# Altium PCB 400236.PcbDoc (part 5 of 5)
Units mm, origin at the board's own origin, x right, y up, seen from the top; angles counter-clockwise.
Board outline 136.53 x 63.5 mm, 4 copper layers (Top Layer, Mid-Layer 1, Mid-Layer 2, Bottom Layer), stack 1.505 mm thick; 340 components, 230 nets, 1369 pads, 1292 vias.
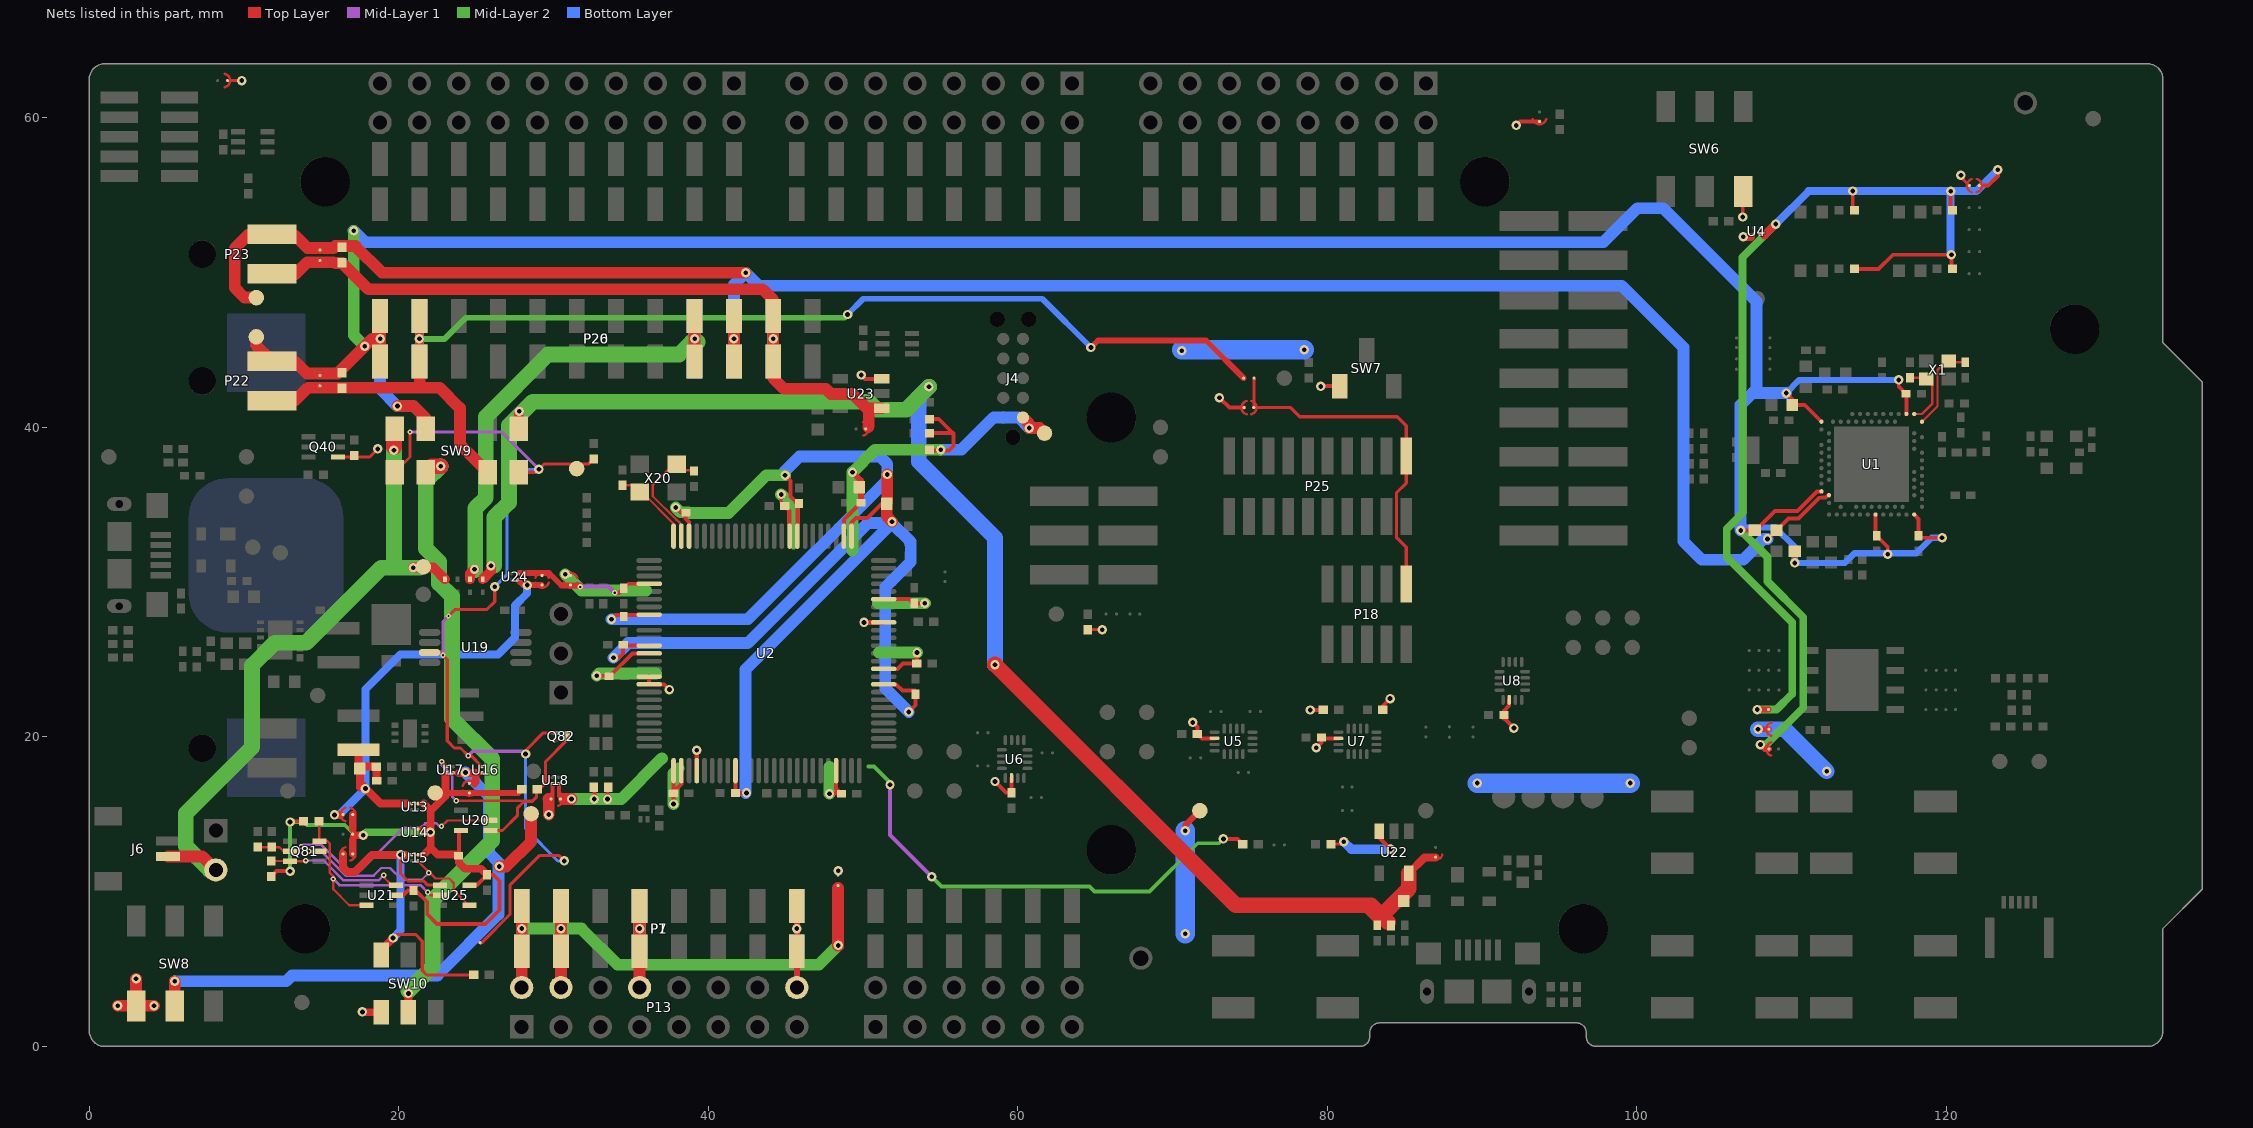
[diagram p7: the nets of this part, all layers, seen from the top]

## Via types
v1: diameter 0.61, hole 0.305, Top Layer to Bottom Layer, tented both sides, 1088 vias
v2: diameter 0.35, hole 0.15, Top Layer to Mid-Layer 1, tented both sides, 180 vias
v3: diameter 0.61, hole 0.305, Top Layer to Bottom Layer, 24 vias

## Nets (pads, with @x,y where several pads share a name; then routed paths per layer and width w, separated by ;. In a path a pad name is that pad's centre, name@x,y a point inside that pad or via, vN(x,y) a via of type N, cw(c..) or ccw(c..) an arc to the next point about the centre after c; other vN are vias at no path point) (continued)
VBUS_NRF': C68.2 C91.2 D81.2 FB60.2 SB80.2 SW9.8 U22.5 | length 100
  Top Layer w0.508: U22.5@85.253,11.198 86.272,12.217 SB80.2@86.995,12.217
  Top Layer w0.635: D81.2@25.425,30.186 25.959,30.719 v1(25.959,31.064) ; SW9.8@27.749,39.906 27.749,41.008 v1(27.788,41.046)
  Top Layer w1.016: v1(58.522,24.673) 74.076,9.119 82.634,9.119 ; 83.497,8.44 85.253,10.196 U22.5@85.253,11.198 ; 83.666,8.271 83.315,8.621 83.223,8.529 82.634,9.119 ; FB60.2@83.91,8.026 82.818,9.119 82.634,9.119
  Mid-Layer 2 w1.016: v1@26.162,31.064 26.162,34.188 27.127,35.154 27.127,40.132 28.651,41.656 50.368,41.656 50.876,41.148 52.781,41.148 v1(54.254,42.621)
  Bottom Layer w1.016: v1(54.254,42.621) 53.594,41.961 53.594,37.795 58.522,32.868 v1(58.522,24.673)
VCORE: C24.2 C26.2 C32.1 C33.2 C35.2 C39.2 C40.2 U2.9 U2.34 U2.52 U2.59 U2.73 U2.83 U2.87 | length 120.1
  Top Layer w0.254: v1(33.747,27.598) 34.038,27.889 U2.83@36.168,27.889 ; v1(33.874,25.121) 34.232,25.121 34.501,25.389 C24.2@34.501,25.959 ; C24.2@34.67,25.9 U2.87@36.179,25.9 ; v1(37.897,34.823) 38.227,34.493 C32.1@38.531,34.493 ; C32.1@38.555,34.493 C32.1@38.531,34.493 ; U2.73@38.754,32.975 38.754,33.89 38.531,34.113 C32.1@38.531,34.493 ; C33.2@41.75,16.383 v1(42.469,16.383) ; C33.2@41.754,16.4 U2.9@41.754,17.825 ; v1(44.958,36.906) 45.314,36.551 45.314,35.525 45.466,35.373 C35.2@45.808,35.031 ; U2.59@45.754,32.975 45.754,34.977 C35.2@45.808,35.031 ; C35.2@45.862,35.085 C35.2@45.808,35.031 ; U2.52@49.254,32.975 49.254,33.861 49.531,34.138 50.292,34.138 51.232,35.077 C39.2@51.522,35.077 ; U2.34@51.329,23.4 52.13,23.4 52.543,22.987 C40.2@53.338,22.987 ; v1(52.949,21.615) 53.381,22.047 C40.2@53.381,22.766 ; C40.2@53.363,22.827 C40.2@53.363,22.987
  Top Layer w0.762: v1(51.562,36.957) 51.562,35.117 C39.2@51.522,35.077 51.522,34.254 v1(51.867,33.909)
  Mid-Layer 2 w0.762: v1(37.897,34.823) 38.202,34.519 38.718,34.519 38.769,34.468 41.3,34.468 43.739,36.906 v1(44.958,36.906)
  Bottom Layer w0.762: v1(33.747,27.598) 42.558,27.598 51.562,36.601 v1(51.562,36.957) 51.562,37.643 51.079,38.125 45.898,38.125 44.958,37.186 v1(44.958,36.906) ; v1(33.874,25.121) 34.813,26.06 42.535,26.06 50.292,33.817 v1@51.867,33.817 ; v1@42.416,16.383 42.408,16.391 42.408,24.359 v1@51.867,33.817 ; v1(52.949,21.615) 51.425,23.139 51.425,29.671 53.076,31.322 53.076,32.608 v1@51.867,33.817
VDBG: P18.1 P25.1 SB59.1 SB60.1 | length 23
  Top Layer w0.203: SB60.1@75.268,43.18 75.268,41.607 75.268,41.3 SB59.1@75.242,41.275 75.417,41.275 77.622,41.275 78.207,40.691 84.506,40.691 85.09,40.107 P25.1@85.09,38.145 85.09,36.398 84.455,35.763 84.455,32.893 85.09,32.258 P18.1@85.09,29.89
VDD: C42.2 C45.2 C48.2 C50.2 Q40.4 R41.1 R52.1 R53.1 R54.2 R68.2 SB9.1 SB17.1 SB31.1 SB37.2 SB38.2 SB47.1 SB59.2 SW6.6 SW7.3 SW8.3 SW10.6 TP37.1 U4.A2 U5.14 U6.14 U7.14 U8.14 U18.A2 U22.3 U23.3 | length 69.9
  Top Layer w0.2: SB47.1@8.923,62.408 v1(9.855,62.408) ; Q40.4@16.063,38.085 18.121,38.085 v1(18.644,38.608) ; R68.2@64.516,26.932 v1(65.448,26.932) ; R54.2@80.231,13.081 80.899,13.081 v1(81.051,13.233) ; v1(120.929,56.286) 120.929,56.179 SB9.1@121.489,55.619
  Top Layer w0.254: 29.941,15.992 U18.A2@29.941,16.95 ; v1(49.886,43.383) 50.129,43.139 U23.3@51.21,43.139 ; v1(58.522,17.12) 59.241,16.4 C45.2@59.588,16.4 59.592,16.404 U6.14@59.592,17.342 ; v1(71.306,20.938) 71.306,20.922 71.595,20.633 C42.2@71.595,20.193 71.88,19.907 U5.14@72.707,19.907 ; v1(73.025,41.91) 73.66,41.275 74.443,41.275 SB59.2@74.618,41.275 ; v1@78.892,21.717 78.918,21.742 R53.1@79.739,21.742 ; v1(79.273,19.304) 79.621,19.652 C48.2@79.621,19.964 79.675,19.91 U7.14@80.715,19.91 ; v1(79.578,42.647) 79.597,42.665 SW7.3@80.8,42.665 ; U22.3@83.353,13.898 83.353,13.472 v1(84.074,12.751) ; R52.1@83.583,21.742 83.583,22.014 v1(84.049,22.479) v1@84.074,22.504 ; C50.2@91.389,21.192 91.508,21.311 C50.2@91.407,21.412 ; U8.14@91.748,22.397 91.737,22.386 91.737,22.021 91.407,21.69 C50.2@91.407,21.412 ; v1(92.05,20.574) 91.411,21.213 91.407,21.217 C50.2@91.407,21.412 ; v1(92.202,59.512) 92.448,59.759 SB31.1@93.701,59.759 ; v1(106.832,53.594) 106.832,54.948 SW6.6@106.869,54.984 ; 107.292,52.225 U4.A2@107.537,52.47
  Top Layer w0.381: v1(70.815,13.945) 70.815,14.3 TP37.1@71.755,15.24 ; v1(107.823,20.498) 108.352,20.498 SB17.1@108.527,20.498
  Top Layer w0.508: v1(17.653,2.235) 17.674,2.214 SW10.6@18.875,2.214 ; v1@106.858,52.299 107.366,52.299
  Top Layer w0.762: v1(1.848,2.628) v1(4.185,2.628) ; SW8.3@3.027,2.559 v1(3.027,4.369) ; 29.679,15.992 29.693,15.979 v1(29.693,14.986)
  Bottom Layer w0.61: v1(81.051,13.233) 81.534,12.751 v1(84.074,12.751)
  Bottom Layer w1.016: v1(107.823,20.498) 109.55,20.498 v1(112.268,17.78)
  Bottom Layer w1.27: v1@70.587,45.009 v1(78.511,45.009) ; v1(70.815,7.29) v1(70.815,13.945) ; v1(89.687,17.018) v1(99.568,17.018)
  other v1: 48.387,11.354 78.892,21.742 70.587,44.958 106.858,52.324
VDD_HV: C19.1 P20.10 P23.1 P26.10 R91.2 SB41.1 TP25.1 U1.Y2 | length 134.4
  Top Layer w0.25: v1@108.562,32.708 108.562,32.891 C19.1@109.014,33.342 109.783,34.112 110.447,34.112 111.793,35.458 111.989,35.458 112.179,35.459 112.337,35.617 U1.Y2@112.414,35.617
  Top Layer w0.762: TP25.1@10.795,48.387 10.033,48.387 9.398,49.022 9.398,51.562 10.306,52.47 P23.1@11.811,52.47 ; P23.1@11.811,52.4 13.284,52.4 14.089,51.595 15.781,51.595 15.9,51.714 17.196,51.714 18.923,49.987 v1(42.418,49.987) ; P20.10@41.656,44.255 v1(41.656,45.72) P20.10@41.656,47.185
  Bottom Layer w0.762: P26.10@41.656,44.255 v1(41.656,45.72) P26.10@41.656,47.185 41.656,49.225 v1(42.418,49.987) 43.256,49.149 99.023,49.149 102.997,45.175 102.997,32.639 104.188,31.448 106.863,31.448 108.206,32.791 v1(108.433,32.791)
VDD_HV': P20.11 P23.2 P26.11 R91.1 SB41.2 SB81.1 U23.1 | length 50.7
  Top Layer w0.762: P23.2@11.811,49.86 13.284,49.86 14.089,50.665 15.781,50.665 ; 15.91,50.613 16.349,50.613 18.042,48.92 43.51,48.92 44.196,48.235 P20.11@44.196,47.185 v1(44.196,45.72) P20.11@44.196,44.255 44.196,43.18 44.882,42.494 47.585,42.494 47.915,42.164 49.301,42.164 50.226,41.239 ; 50.333,40.016 50.368,40.051 50.368,41.097 50.226,41.239 ; U23.1@51.21,41.239 50.226,41.239
  Bottom Layer w0.762: P26.11@44.196,44.255 v1(44.196,45.72) P26.11@44.196,47.185
VDD_NRF: C6.1 C7.1 C8.1 C12.1 C14.1 L4.1 P20.1 P22.1 P26.1 R90.2 SB18.1 SB40.1 SW9.6 TP24.1 U1.A22 U1.AD14 U1.AD23 U1.B1 U1.W1 | length 200.6
  Top Layer w0.25: v1(106.714,33.342) C6.1@107.613,33.342 107.664,33.342 108.916,34.595 110.371,34.595 111.641,35.865 U1.W1@111.914,35.865 ; v1(109.639,42.217) 110.039,41.817 C14.1@110.039,41.444 110.837,41.444 U1.B1@111.914,40.367 ; v1@110.189,31.117 L4.1@110.189,31.992 ; C7.1@115.414,32.992 U1.AD14@115.414,34.367 ; C7.1@115.49,32.992 116.205,32.277 v1@116.205,32.004 ; v1(116.915,43.067) 116.915,42.641 C12.1@117.389,42.167 117.414,42.142 U1.A22@117.414,40.867 ; U1.AD23@117.914,34.367 118.189,34.092 C8.1@118.189,32.992 118.313,32.868 v1(119.71,32.868)
  Top Layer w0.381: v1(107.975,19.507) 108.255,19.228 108.352,19.228 SB18.1@108.527,19.228
  Top Layer w0.762: TP24.1@10.795,45.847 10.795,45.286 P22.1@11.811,44.27 13.284,44.27 14.064,43.49 16.058,43.49 v1(17.805,45.237) 18.288,45.72 v1(18.796,45.72) ; P20.1@18.796,44.255 v1(18.796,45.72) ; P20.1@18.796,47.185 v1(18.796,45.72) ; v1(19.914,41.377) 20.955,41.377 21.749,40.583 SW9.6@21.749,39.906
  Mid-Layer 2 w0.508: v1(106.714,33.342) 108.433,31.623 108.433,30.048 110.744,27.737 110.744,21.895 108.356,19.507 v1(107.975,19.507)
  Mid-Layer 2 w0.762: v1@17.094,52.685 17.094,45.949 v1(17.805,45.237)
  Bottom Layer w0.4: v1(106.714,33.342) 106.894,33.522 108.946,33.522 110.189,32.28 v1@110.189,31.318 ; v1(109.639,42.217) 110.489,43.067 v1@116.839,43.067 ; v1(110.189,31.244) 113.427,31.244 114.054,31.871 118.054,31.871 119.05,32.868 v1(119.71,32.868)
  Bottom Layer w0.762: v1(17.084,52.71) 17.838,51.956 97.828,51.956 100.025,54.153 101.702,54.153 107.729,48.126 107.729,42.493 ; P26.1@18.796,47.185 v1(18.796,45.72) P26.1@18.796,44.255 18.796,42.494 v1(19.914,41.377) ; v1(106.714,33.342) 106.692,33.364 106.692,41.456 107.729,42.493 ; v1(109.639,42.217) 107.729,42.217 107.729,42.493
  other v1: 116.205,31.801
VDD_NRF': P20.2 P22.2 P26.2 R90.1 SB40.2 SB60.2 SW9.3 | length 82.3
  Top Layer w0.381: v1(64.719,45.161) 65.176,45.618 72.154,45.618 SB60.2@74.592,43.18
  Top Layer w0.508: P20.2@21.336,44.255 v1(21.336,45.72) P20.2@21.336,47.185
  Top Layer w0.762: P22.2@11.811,41.73 13.284,41.73 14.115,42.561 21.361,42.561 ; P20.2@21.336,44.255 21.361,44.23 21.361,42.561 ; SW9.3@25.749,37.106 23.952,38.903 23.952,41.25 22.641,42.561 21.361,42.561
  Mid-Layer 2 w0.381: v1(21.336,45.72) 22.963,45.72 24.325,47.081 48.783,47.081 v1(48.997,47.295)
  Bottom Layer w0.381: v1(48.997,47.295) 50.013,48.311 61.57,48.311 v1(64.719,45.161)
  Bottom Layer w0.508: P26.2@21.336,44.255 v1(21.336,45.72) P26.2@21.336,47.185
VDD_NRF_SENSE: Q82.1 R88.1 SB58.1 SW9.1 SW9.4 TP33.1 U16.B2 U19.3 | length 67.2
  Top Layer w0.203: SW9.1@19.749,37.106 20.726,38.084 v2(20.726,39.7) ; U19.3@21.993,25.456 22.677,25.456 v2(22.86,25.273) 23.129,25.004 23.129,19.747 23.591,19.284 23.987,19.284 v2(24.486,18.786) 24.673,18.786 U16.B2@25.378,18.082 ; v2(23.216,27.813) 23.647,28.245 25.705,28.245 26.2,28.74 v1(26.2,29.705) ; SB58.1@25.255,6.706 25.356,6.706 27.178,8.528 27.178,10.408 29.117,12.347 30.325,12.347 v1(30.683,11.989) ; SW9.4@27.749,37.106 28.877,37.106 v1(29.058,37.287) 29.413,37.643 32.275,37.643 R88.1@32.588,37.956 ; v1(28.194,18.898) 28.194,19.126 29.333,20.266 Q82.1@30.155,20.266
  Mid-Layer 1 w0.203: v2(20.726,39.7) 26.645,39.7 v1(29.058,37.287) ; v2(22.86,25.273) 22.86,27.457 v2(23.216,27.813) ; v2(24.486,18.786) 24.775,19.075 28.016,19.075 v1(28.194,18.898)
  Bottom Layer w0.203: v1(26.2,29.705) 27,30.505 27,36.297 27.991,37.287 v1(29.058,37.287) ; v1(28.194,18.898) 28.194,14.078 30.283,11.989 v1(30.683,11.989)
VDD_PER: R47.2 R48.2 R50.2 R51.2 SB9.2 SB16.1 U4.A1 | length 71
  Top Layer w0.25: U4.A1@107.95,52.476 108.235,52.476
  Top Layer w0.254: R50.2@113.94,50.353 R50.2@114.059,50.234 115.614,50.234 116.535,51.156 v1(120.316,51.156) 120.316,50.302 R51.2@120.384,50.234 ; 113.94,54.443 v1(113.94,55.271) 113.94,54.163 R47.2@114.059,54.044 ; v1(120.265,55.264) 120.265,54.163 R48.2@120.384,54.044 ; SB9.2@122.114,55.619 122.289,55.619 122.684,55.619 123.317,56.252 v1(123.317,56.642)
  Top Layer w0.381: v1(107.772,21.768) SB16.1@108.501,21.768
  Top Layer w0.508: 108.229,52.4 v1(108.966,53.137)
  Mid-Layer 2 w0.508: v1(107.772,21.768) 109.017,21.768 110.033,22.784 110.033,27.395 105.804,31.623 105.804,33.44 106.819,34.455 106.819,50.99 v1(108.966,53.137)
  Bottom Layer w0.508: v1(108.966,53.137) 111.093,55.264 v1(120.265,55.264) ; v1@120.265,51.156 v1(120.265,55.264) ; v1(123.317,56.642) 121.939,55.264 v1(120.265,55.264)
VDD_SAM: C25.2 C31.2 C34.2 C36.2 C37.2 C38.2 C41.2 C43.2 J4.1 R20.2 R21.2 R49.2 R64.2 R65.2 R66.2 SB37.1 SB49.1 TP35.1 U2.1 U2.2 U2.4 U2.22 U2.36 U2.42 U2.45 U2.53 U2.60 U2.88 U2.91 U2.92 U18.A1 | length 117.8
  Top Layer w0.152: U2.88@36.179,25.4 U2.88@36.347,25.4
  Top Layer w0.203: v1(44.704,35.67) 44.704,35.161 C34.2@44.94,34.925
  Top Layer w0.254: 30.347,16.196 30.347,16.407 U18.A1@30.347,16.958 ; v1@32.636,16.002 R20.2@32.636,16.747 ; v1(32.791,23.952) 33.645,23.952 35.093,25.4 U2.88@36.179,25.4 ; v1(33.486,15.985) R21.2@33.486,16.747 ; U2.91@36.179,23.9 U2.92@36.179,23.4 37.151,23.4 v1(37.489,23.062) ; U2.1@37.754,17.825 37.754,16.358 37.756,16.356 v1(37.756,15.666) ; C31.2@37.76,16.459 38.254,16.954 U2.2@38.254,17.825 ; C34.2@44.94,34.925 45.254,34.611 U2.60@45.254,32.975 ; v1(47.828,16.332) C36.2@48.598,16.332 48.254,16.676 U2.22@48.254,17.825 ; U2.53@48.754,32.975 48.754,34.032 49.017,34.295 49.763,35.041 C37.2@49.763,35.128 ; U2.36@51.329,24.4 52.228,24.4 52.568,24.74 C41.2@53.465,24.74 53.482,24.757 v1(53.482,25.451) ; U2.42@51.329,27.4 U2.42@51.348,27.381 ; U2.45@51.329,28.9 52.98,28.9 C43.2@53.17,28.71 ; C43.2@53.305,28.634 v1(53.99,28.634) ; R64.2@54.293,38.557 R64.2@54.297,38.557 54.297,38.506 55.55,38.506 55.829,38.786 55.829,39.599 55.804,39.624 ; R65.2@54.293,39.624 R65.2@54.297,39.624 55.804,39.624 ; R66.2@54.297,40.538 54.889,40.538 55.804,39.624 ; v1(73.279,13.411) 74.201,13.411 R49.2@74.532,13.081
  Top Layer w0.305: U2.4@39.254,17.825 v1(39.254,19.146) ; v1(50.059,27.4) U2.42@51.329,27.4
  Top Layer w0.381: v1(49.317,37.109) 49.868,36.559 C37.2@49.868,35.128
  Top Layer w0.762: 30.678,15.992 v1(31.16,15.992) ; J4.1@60.325,40.64 60.731,40.234 v1(60.731,39.954) 61.417,39.954 TP35.1@61.747,39.624
  Mid-Layer 1 w0.254: v1(51.74,16.916) 51.74,13.665 v1(54.432,10.973)
  Mid-Layer 2 w0.254: 50.343,18.085 50.698,18.085 51.74,17.043 v1(51.74,16.916) ; v1(54.432,10.973) 55.07,10.335 64.625,10.335 64.94,10.02 68.513,10.02 71.622,13.129 72.997,13.129 v1(73.279,13.411)
  Mid-Layer 2 w0.762: v1(30.759,30.505) 31.801,29.464 35.992,29.464 ; v1@31.16,15.985 v1(33.486,15.985) 34.377,15.985 37.004,18.612 ; v1(32.791,23.952) 32.937,24.098 36.623,24.098 ; v1(37.756,15.666) 37.756,17.639 38.075,17.958 ; v1(44.704,35.67) 45.513,34.861 45.513,32.48 ; v1(47.828,16.332) 47.828,18.053 ; 49.317,32.045 v1(49.317,37.109) 50.765,38.557 v1(55.008,38.557) ; 50.948,28.634 v1(53.99,28.634) ; 51.024,25.451 v1(53.482,25.451)
  Bottom Layer w0.762: v1(55.008,38.557) 56.354,38.557 58.437,40.64 60.046,40.64 v1(60.731,39.954)
  other v1: 32.636,15.985
VDD_UTMI: C28.2 SB48.1 SB49.2 U2.79 U24.A1 | length 9.2
  Top Layer w0.254: v2@31.681,29.787 v2@31.775,29.693 ; v2(33.95,29.312) 34.237,29.312 C28.2@34.534,29.608 ; C28.2@34.542,29.616 34.826,29.9 U2.79@36.179,29.9
  Top Layer w0.381: 27.788,30.596 29.704,30.596 30.513,29.787 30.757,29.787 31.422,29.787 v2@31.681,29.787
  Mid-Layer 1 w0.254: v2@31.725,29.718 33.543,29.718 v2(33.95,29.312)
  other v2: 31.725,29.693
VEXT: R92.1 SB36.2 SW10.3 U15.A1 U25.1 | length 24.1
  Top Layer w0.203: SW10.3@18.875,5.914 SW10.3@18.875,6.251 ; 19.84,7.241 21.08,7.241 21.514,6.807 21.514,4.928 21.819,4.623 R92.1@24.849,4.623 ; v1(20.117,12.382) 20.117,11.176 20.599,10.693 21.615,10.693 21.88,10.429 U25.1@22.672,10.429
  Top Layer w0.245: 20.498,12.392 U15.A1@20.831,12.392
  Top Layer w0.508: SB36.2@16.393,12.446 16.393,12.183 16.403,12.173 16.403,12.159 ; 16.403,12.159 16.403,11.563 16.688,11.278 17.17,11.278 18.275,12.382 v1(20.117,12.382) 20.488,12.382 ; SW10.3@18.875,6.251 v1(19.634,7.01)
  Bottom Layer w0.508: v1(19.634,7.01) 20.117,7.493 v1(20.117,12.382)
VEXT_EN: Q81.5 U15.B2 U25.4 | length 14.5
  Top Layer w0.152: v2(14.199,12.624) Q81.5@14.869,12.624 ; U15.B2@21.231,11.992 22.367,10.856 23.256,10.856 23.546,10.566 23.546,10.104 U25.4@24.521,9.129
  Mid-Layer 1 w0.152: v2(14.199,12.624) 14.979,12.624 16.564,11.039 18.379,11.039 18.87,11.529 19.433,11.529 20.193,10.77 21.488,10.77 v2(21.946,11.227)
VEXT_EN_INV: Q81.3 R89.2 U21.6 | length 9.1
  Top Layer w0.152: R89.2@11.76,11.981 12.962,11.981 Q81.3@12.969,11.974 13.955,11.974 v2(13.995,12.014) ; v2(19.025,11.074) 19.025,10.937 19.533,10.429 U21.6@19.822,10.429
  Mid-Layer 1 w0.152: v2(13.995,12.014) 15.157,12.014 16.437,10.734 18.684,10.734 v2(19.025,11.074)
VIN: P1.8 P7.8 P13.16 | length 8.2
  Top Layer w0.381: P13.16@45.72,3.81 P1.8@45.72,6.155 v1(45.72,7.62) P1.8@45.72,9.085
  Bottom Layer w0.381: P7.8@45.72,6.155 v1(45.72,7.62) P7.8@45.72,9.085
VIN3-5V: D83.2 P20.9 P26.9 | length 32.5
  Top Layer w0.635: D83.2@24.613,30.186 24.613,30.556 v1(24.892,30.836)
  Top Layer w0.762: P20.9@39.116,44.255 v1(39.116,45.72) P20.9@39.116,47.185
  Mid-Layer 2 w1.016: v1@24.943,30.785 24.943,34.773 25.629,35.458 25.629,40.691 29.642,44.704 38.1,44.704 38.913,45.517 v1@39.319,45.517
  Bottom Layer w0.762: P26.9@39.116,44.255 v1(39.116,45.72) P26.9@39.116,47.185
VIO: P1.1 P1.2 P1.4 P7.1 P7.2 P7.4 P13.2 P13.4 P13.8 SB38.1 | length 54.1
  Top Layer w0.381: v1(35.56,7.62) P1.4@35.56,9.085
  Top Layer w0.762: P13.2@27.94,3.81 P1.1@27.94,6.155 P1.1@27.94,9.085 ; P13.4@30.48,3.81 v1(30.48,7.62) P1.2@30.48,9.085 ; P13.8@35.56,3.81 P1.4@35.56,9.085 ; v1(48.387,6.528) 48.387,10.236
  Mid-Layer 2 w0.762: v1(27.94,7.62) v1(30.48,7.62) 31.801,7.62 34.138,5.283 35.535,5.283 ; v1(35.56,7.62) 35.56,5.309 35.535,5.283 ; v1(48.387,6.528) 47.142,5.283 35.535,5.283
  Bottom Layer w0.762: P7.1@27.94,6.155 P7.1@27.94,9.085 ; P7.2@30.48,6.155 P7.2@30.48,9.085 ; P7.4@35.56,6.155 P7.4@35.56,9.085
VLI-ION: D82.2 J6.2 P27.2 SW9.5 TP31.1 | length 44.1
  Top Layer w0.635: v1(20.93,30.937) 22.235,30.937 D82.2@22.987,30.186
  Top Layer w0.762: J6.2@5.105,12.276 7.307,12.276 P27.2@8.179,11.405
  Top Layer w1.016: v1@19.685,38.735 19.685,39.842 SW9.5@19.749,39.906
  Mid-Layer 2 w1.016: P27.2@8.179,11.405 7.772,11.405 6.236,12.941 6.236,15.05 10.516,19.329 10.516,24.613 11.989,26.086 14.021,26.086 18.872,30.937 19.685,30.937 ; v1(19.685,38.532) 19.685,30.937 ; 21.336,30.937 v1(20.93,30.937) 19.685,30.937
VREG: C87.2 C88.2 L81.2 R82.2 SB34.2 SB48.2 U13.A1 U24.A2 | length 34.2
  Top Layer w0.245: 20.498,15.694 U13.A1@20.831,15.694
  Top Layer w0.381: 27.788,30.062 27.774,30.062 28.024,29.812 v1(28.296,29.812) 28.908,29.812 SB48.2@29.235,29.812
  Top Layer w0.508: v1(15.85,14.961) 16.228,14.961 16.23,14.959 ; L81.2@17.399,19.093 17.399,18.049 C88.2@17.49,17.958 ; 17.49,16.739 C88.2@17.49,17.958 ; 17.49,17.018 v1(17.845,16.662) 18.814,15.694 20.498,15.694 ; C87.2@18.575,17.17 18.55,17.196 R82.2@18.55,18.085 17.617,18.085 C88.2@17.49,17.958
  Bottom Layer w0.508: v1(15.85,14.961) 16.144,14.961 v1(17.845,16.662) 17.845,23.078 20.091,25.324 26.406,25.324 27.508,26.426 27.508,28.499 28.296,29.286 v1(28.296,29.812)
VREG_EN: Q81.2 R83.2 R85.1 U20.2 | length 17.5
  Top Layer w0.152: R85.1@10.893,12.886 10.893,12.87 12.294,12.87 12.541,12.624 Q81.2@12.969,12.624 13.411,12.624 v2(13.691,12.903) ; v2(22.758,14.224) 23.139,14.605 U20.2@25.918,14.605
  Mid-Layer 1 w0.152: v2(13.691,12.903) 13.812,13.025 15.008,13.025 16.69,11.343 17.504,11.343 20.283,14.122 21.412,14.122 21.717,14.427 22.428,14.427 22.631,14.224 v2(22.758,14.224)
VREG_EN_INV: Q81.6 R86.2 U21.3 U25.2 | length 15
  Top Layer w0.152: R86.2@14.851,14.554 14.851,13.292 15.359,13.292 15.548,13.103 15.548,11.205 15.773,10.98 v2(15.773,10.82) 15.773,10.16 16.804,9.129 U21.3@17.922,9.129 ; v2(21.869,9.957) 22.047,9.779 U25.2@22.672,9.779
  Mid-Layer 1 w0.152: v2(15.773,10.82) 16.165,10.429 21.397,10.429 v2(21.869,9.957)
VSENSE_SW_OUT: SB39.1 SW8.2 TP30.1 U16.A2 U17.A1 | length 41.3
  Top Layer w0.25: U17.A1@23.517,17.682 23.876,17.682 ; 24.971,17.682 U16.A2@25.378,17.682
  Top Layer w0.508: 23.876,17.682 24.971,17.682 24.971,17.08 24.892,17
  Top Layer w0.762: SW8.2@5.528,2.609 v1(5.528,4.216) ; v1(26.492,11.633) 26.949,11.633 28.55,13.233 TP30.1@28.55,14.859
  Bottom Layer w0.762: v1(5.528,4.216) 12.727,4.216 13.106,4.596 22.503,4.596 26.441,8.534 26.441,11.909 25.829,12.521 25.829,16.182 v1(24.308,17.704)
VSRC_NRF: SW9.2 SW10.5 | length 40.6
  Top Layer w0.508: SW10.5@20.625,2.214 v1(20.625,3.429)
  Top Layer w1.016: SW9.2@21.749,37.106 22.133,37.49 v1(22.708,37.49)
  Mid-Layer 2 w1.016: v1@20.625,3.607 22.174,5.156 22.174,9.449 26.035,13.31 26.035,18.593 23.444,21.184 23.444,29.083 22.606,29.921 22.606,31.32 21.749,32.177 21.749,36.532 v1(22.708,37.49)
VSUPPLY: C89.2 C90.2 C93.2 R86.1 R87.1 R89.1 SB34.1 SB35.1 SB36.1 SB39.2 TP29.1 U13.A2 U14.A2 U15.A2 U17.A2 U20.5 U21.5 U25.5 | length 49.4
  Top Layer w0.245: U15.A2@21.231,12.392 21.615,12.392 ; U14.A2@21.231,14.043 21.615,14.043 ; U13.A2@21.231,15.694 21.641,15.694
  Top Layer w0.254: R89.1@11.76,10.981 12.108,11.328 v1(12.979,11.328) ; v1(12.979,14.503) 13.03,14.554 R86.1@13.851,14.554 ; U21.5@19.822,9.779 20.295,9.779 20.591,10.076 C89.2@20.955,10.076 21.09,10.076 21.842,9.324 21.842,8.562 22.481,7.922 25.601,7.922 26.497,8.819 26.497,10.688 26.111,11.074 25.722,11.074 C90.2@25.705,11.092 25.042,10.429 U25.5@24.521,10.429 ; C93.2@23.884,12.395 23.884,13.821 U20.5@24.018,13.955
  Top Layer w0.381: 23.012,16.386 23.012,16.391 23.937,16.391 23.942,16.386 24.201,16.386 24.922,16.386 27.722,16.386 R87.1@27.948,16.612
  Top Layer w0.457: SB36.1@17.028,12.446 17.028,13.365 ; 17.028,14.067 SB34.1@17.028,14.986
  Top Layer w0.508: SB35.1@17.091,13.65 v1(17.704,13.65) ; 21.615,12.392 22.07,12.846 ; 21.615,14.043 22.067,14.043 v1@22.07,14.046 ; 21.641,15.694 21.641,15.666 22.07,15.237 ; 23.012,16.386 23.012,16.18 22.07,15.237 ; 23.012,16.391 23.012,17.501 ; C90.2@25.705,11.092 25.316,11.481 24.282,11.481 23.884,11.879 23.884,12.395 22.521,12.395 22.07,12.846 ; 22.07,12.846 v1@22.07,14.046 ; v1@22.07,14.046 22.07,15.237
  Mid-Layer 2 w0.254: v1(12.979,11.328) v1(12.979,14.503) 13.868,14.503 14.072,14.3 16.51,14.3 17.16,13.65 v1(17.704,13.65)
  Mid-Layer 2 w0.508: v1(17.704,13.65) 17.897,13.843 v1(22.047,13.843)
VSUPPLY_EN: Q82.3 R87.2 U17.B2 U20.1 | length 16.8
  Top Layer w0.152: v2(22.784,18.415) U17.B2@23.117,18.082 ; v2(23.724,15.875) 27.983,15.875 28.059,15.799
  Top Layer w0.203: U20.1@25.918,13.955 26.706,13.955 27.661,14.91 27.661,15.4 28.059,15.799 28.11,15.85 28.626,15.85 28.905,16.129 28.905,16.62 29.066,16.62 29.489,17.043 29.489,18.415 30.855,19.781 Q82.3@30.855,20.041
  Mid-Layer 1 w0.152: v2(22.784,18.415) 22.784,18.161 23.444,17.501 23.444,16.154 v2(23.724,15.875)
XC1: C1.1 U1.B24 X1.1 | length 5.8
  Top Layer w0.152: U1.B24@118.414,40.367 119.414,41.367 119.414,43.717 119.909,44.213 C1.1@121.203,44.213
XC2: C2.1 U1.A23 X1.3 | length 4.3
  Top Layer w0.152: C2.1@117.647,43.213 118.625,43.213 X1.3@118.7,43.138 119.089,42.749 119.089,41.538 118.418,40.867 U1.A23@117.914,40.867
XIN: C29.1 U2.75 X20.3 | length 5.1
  Top Layer w0.152: C29.1@34.458,36.254 35.162,36.254 X20.3@35.575,35.841 ; X20.3@35.575,35.838 35.694,35.838 37.754,33.778 U2.75@37.754,32.975
XOUT: C30.1 U2.74 X20.1 | length 7.5
  Top Layer w0.152: U2.74@38.254,32.975 38.254,33.729 38.1,33.884 37.955,34.029 37.934,34.029 36.414,35.549 36.414,36.287 37.746,37.619 X20.1@37.963,37.619 38.354,37.228 C30.1@39.081,37.228
pads on no net: Bat1.0 Fid1.0 Fid2.0 J2.4 J2.6@1.944,28.45 J2.6@1.944,35.05 J3.4 J3.6@86.429,3.557 J3.6@93.029,3.557 J4.0 J4.7 J4.9 J5.0 J5.1 J5.3 J5.5 J6.0 P18.7 P18.8 P19.7 P19.8 P21.0 P22.0 P23.0 P25.7 P25.8 P25.11 P25.13 SW8.1 U2.6 U2.8 U2.10 U2.11 U2.13 U2.15 U2.16 U2.19 U2.25 U2.26 U2.28 U2.29 U2.30 U2.31 U2.32 U2.33 U2.37 U2.44 U2.48 U2.49 U2.50 U2.58 U2.64 U2.69 U2.86 U2.93 U2.94 U2.95 U2.96 U2.99 U2.100 U5.1 U5.5 U5.9 U5.13 U6.1 U6.5 U6.9 U6.13 U7.7 U7.11 U8.11 U8.12 U8.13 U12.5 U22.4 U23.4
copper on no net: | length 3.6
  Bottom Layer w0.254: 38.252,53.76 38.252,57.379

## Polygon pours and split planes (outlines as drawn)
VDD on Mid-Layer 2 "Mid_Layer_2-VDD" (solid, remove dead copper, pour order 10): -3.81,-3.81 -3.81,68.58 138.43,68.58 138.43,-3.81
VDD_SAM on Mid-Layer 2 "Mid_Layer_2-VDD_SAM" (solid, pour order 8): 35.837,33.12 35.837,17.379 51.555,17.379 51.555,33.12
GND on Bottom Layer "Bottom_Layer-GND" (solid, remove dead copper, pour order 6): -3.81,-3.81 -3.81,68.58 138.43,68.58 138.43,-3.81
GND on Mid-Layer 1 "Mid_Layer_1-GND" (solid, remove dead copper, pour order 7): -3.81,-3.81 -3.81,68.58 138.43,68.58 138.43,-3.81
GND on Top Layer "Top_Layer-GND" (solid, remove dead copper, pour order 12): -3.81,-3.81 -3.81,68.58 138.43,68.58 138.43,-3.81

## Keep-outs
Top Layer:
  lines w0.152: 16.336,8.023 ccw(c13.97,7.62) 16.339,8.006 ; 68.406,13.103 ccw(c66.04,12.7) 68.409,13.086 ; 90.89,53.591 cw(c90.17,55.88) 91.893,54.209
Mid-Layer 1:
  circle w0.152: c66.04,12.7 r2.4
  circle w0.152: c90.17,55.88 r2.4
  circle w0.152: c13.97,7.62 r2.4
Mid-Layer 2:
  circle w0.152: c90.17,55.88 r2.4
  circle w0.152: c13.97,7.62 r2.4
  lines w0.152: 65.381,10.392 cw(c66.04,12.7) 66.72,10.398
Bottom Layer:
  circle w0.152: c66.04,12.7 r2.4
  circle w0.152: c90.17,55.88 r2.4
  circle w0.152: c13.97,7.62 r2.4
Keep-Out Layer:
  circle w0.152: c128.27,46.355 r2.4
  circle w0.152: c15.24,55.88 r2.4
  circle w0.152: c66.04,40.64 r2.4
  circle w0.152: c96.52,7.62 r2.4
  circle w0.1: c13.967,0 r0.3
  circle w0.1: c15.067,0 r0.3
  circle w0.1: c16.167,0 r0.3
  circle w0.1: c123.987,0 r0.3
  circle w0.1: c122.887,0 r0.3
  circle w0.1: c121.787,0 r0.3
  circle w0.1: c136.526,42.025 r0.3
  circle w0.1: c136.526,40.926 r0.3
  circle w0.1: c136.526,39.826 r0.3
  circle w0.1: c121.787,63.5 r0.3
  circle w0.1: c122.887,63.5 r0.3
  circle w0.1: c123.987,63.5 r0.3
  circle w0.1: c13.967,63.5 r0.3
  circle w0.1: c15.067,63.5 r0.3
  circle w0.1: c16.167,63.5 r0.3
  circle w0.1: c0,48.692 r0.3
  circle w0.1: c0,49.792 r0.3
  circle w0.1: c0,50.891 r0.3
  circle w0.1: c0,17.705 r0.3
  circle w0.1: c0,18.804 r0.3
  circle w0.1: c0,19.904 r0.3
  lines w0.254: 0,1.016 ccw(c1.016,1.016) 1.016,0 82.099,0 ccw(c82.099,0.635) 82.734,0.635 82.734,0.889 cw(c83.369,0.889) 83.369,1.524 96.09,1.524 cw(c96.09,0.889) 96.725,0.889 96.725,0.635 ccw(c97.36,0.635) 97.36,0 132.969,0 ccw(c132.969,1.016) 133.985,1.016 133.985,7.62 136.525,10.16 136.525,42.926 133.985,45.466 133.985,62.484 ccw(c132.969,62.484) 132.969,63.5 1.016,63.5 ccw(c1.016,62.484) 0,62.484 0,1.016

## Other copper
Top Layer:
  rectangle net ANT: 134.92,20.343 136.19,21.105
  rectangle net GND: 8.484,25.527 12.167,26.594
  rectangle net GND: 11.557,24.308 13.132,28.397
  pour cut-out: 24.34,36.179 34.579,36.18 cw(c34.58,33.644) 36.375,35.436 38.509,33.302 cw(c36.718,31.508) 39.253,31.506 39.253,31.237 cw(c37.043,31.237) 37.043,29.027 34.834,29.027 cw(c34.833,30.64) 33.693,29.5 31.579,31.613 ccw(c30.81,30.846) 30.808,31.933 24.328,31.933 cw(c135.433,33.762)
  pour cut-out: 13.807,35.551 cw(c15.316,34.043) 15.316,36.176 25.908,36.176 25.908,31.939 16.574,31.92 ccw(c16.747,30.866) 15.922,31.544 14.783,30.405 13.807,30.405
  pour cut-out: 9.86,34.155 11.774,34.155 11.938,34.155 11.938,30.013 11.169,30.013 cw(c11.169,30.94) 10.513,30.284 ccw(c10.035,29.809) 10.034,30.482 5.422,30.482 5.422,34.158 7.355,34.158 7.411,34.148 7.465,34.13 7.51,34.104 7.553,34.069 7.584,34.023 7.602,33.98 7.607,33.934 7.607,32.685 9.354,32.685 9.354,33.65 cw(c9.86,33.65)
  pour cut-out: 11.677,34.155 12.282,34.155 ccw(c12.282,34.476) 12.509,34.249 13.819,35.56 14.795,35.56 14.795,30.414 cw(c13.804,31.435) 13.782,30.013 11.677,30.013
  pour cut-out: 90.658,5.004 90.658,7.315 96.62,7.315 96.62,5.004
  pour cut-out: 91.161,32.131 91.161,33.401 89.891,33.401 89.891,32.131
  pour cut-out: 107.164,32.217 107.164,33.617 110.834,33.617 110.834,32.217
  pour cut-out: 110.664,31.367 110.664,32.867 113.164,32.867 113.164,31.367
  pour cut-out: 115.414,36.867 115.414,38.367 117.914,38.367 117.914,36.867
  pour cut-out: 117.737,33.63 116.676,34.691 118.444,36.458 119.505,35.398
  pour cut-out: 60.528,30.937 68.073,30.937 68.071,32.715 60.528,32.715
  pour cut-out: 129.92,-1.27 136.786,-1.27 136.748,45.415 129.925,45.415
  pour cut-out: -0.229,28.204 2.824,28.204 2.818,35.281 -0.228,35.281
  pour cut-out: 28.981,25.603 28.981,26.873 27.711,26.873 27.711,25.603
  pour cut-out: 118.567,26.975 117.297,26.975 117.297,25.705 118.567,25.705
  pour cut-out: 11.252,51.765 9.982,51.765 9.982,50.495 11.252,50.495
  pour cut-out: 86.385,35.687 85.115,35.687 85.115,34.417 86.385,34.417
  pour cut-out: 60.757,53.086 48.387,53.086 48.387,51.816 60.757,51.816
  pour cut-out: 107.163,43.256 107.163,44.526 105.054,44.526 105.054,43.256
  pour cut-out: 22.149,1.168 22.149,2.438 20.879,2.438 20.879,1.168
  pour cut-out: 20.447,5.715 20.447,6.985 19.177,6.985 19.177,5.715
  pour cut-out: 20.218,1.143 20.218,3.264 18.948,3.264 18.948,1.143
  pour cut-out: 11.252,43.635 9.982,43.635 9.982,42.365 11.252,42.365
  pour cut-out: 118.496,37.293 121.239,37.293 121.239,39.142 120.439,39.142 120.439,40.188 118.496,40.188
Mid-Layer 1:
  pour cut-out: 110.28,18.44 107.467,18.44 107.467,25.333 110.28,25.333
  pour cut-out: 28.315,29.007 28.315,31.318 32.137,31.318 32.137,29.007
  pour cut-out: 92.078,58.763 92.078,61.074 95.377,61.074 95.377,58.763
  pour cut-out: 48.603,38.976 48.603,41.288 50.978,41.288 50.978,38.976
  pour cut-out: 85.782,11.379 85.782,13.691 88.157,13.691 88.157,11.379
  pour cut-out: 110.28,27.254 110.28,21.336 106.28,21.336 106.28,27.254
  pour cut-out: 129.92,-1.27 136.786,-1.27 136.748,45.415 129.925,45.415
  pour cut-out: 121.71,25.984 121.71,20.066 117.71,20.066 117.71,25.984
  pour cut-out: 104.44,46.723 110.357,46.723 110.357,42.723 104.44,42.723
  pour cut-out: 15.45,11.278 15.45,16.104 17.824,16.104 17.824,11.278
  pour cut-out: 23.4,15.494 23.4,17.805 25.774,17.805 25.774,15.494
  pour cut-out: 75.724,11.938 75.724,14.249 78.098,14.249 78.098,11.938
  pour cut-out: 56.725,19.202 56.725,21.514 59.099,21.514 59.099,19.202
  pour cut-out: 56.598,17.094 56.598,19.406 58.972,19.406 58.972,17.094
  pour cut-out: 60.618,17.843 60.618,20.155 62.992,20.155 62.992,17.843
  pour cut-out: 59.969,14.973 59.969,17.285 62.344,17.285 62.344,14.973
  pour cut-out: 64.878,26.695 64.878,29.007 68.656,29.007 68.656,26.695
  pour cut-out: 120.612,48.831 120.612,57.137 122.987,57.137 122.987,48.831
  pour cut-out: 7.449,61.138 7.449,63.449 9.823,63.449 9.823,61.138
  pour cut-out: 70.263,17.45 70.263,19.761 72.637,19.761 72.637,17.45
  pour cut-out: 71.438,20.587 71.438,22.898 73.812,22.898 73.812,20.587
  pour cut-out: 74.175,20.512 74.175,22.823 76.549,22.823 76.549,20.512
  pour cut-out: 73.369,16.612 73.369,18.923 75.744,18.923 75.744,16.612
  pour cut-out: 28.448,14.884 28.448,17.196 31.747,17.196 31.747,14.884
  pour cut-out: 54.212,29.184 54.212,31.495 56.586,31.495 56.586,29.184
  pour cut-out: 80.042,13.995 80.042,18.161 82.416,18.161 82.416,13.995
  pour cut-out: 84.979,19.177 84.979,21.488 90.941,21.488 90.941,19.177
  pour cut-out: 13.678,49.898 13.678,52.21 16.053,52.21 16.053,49.898
  pour cut-out: 13.704,41.87 13.704,44.181 16.078,44.181 16.078,41.87
  pour cut-out: 47.232,9.614 47.232,11.925 49.606,11.925 49.606,9.614
  pour cut-out: 23.654,5.486 23.654,7.798 26.028,7.798 26.028,5.486
  pour cut-out: 73.641,41.986 73.641,44.298 76.016,44.298 76.016,41.986
  pour cut-out: 73.667,40.03 73.667,42.342 76.041,42.342 76.041,40.03
  pour cut-out: 131.445,36.392 119.918,36.392 119.918,40.392 131.445,40.392
Mid-Layer 2:
  pour cut-out: 129.92,-1.27 136.786,-1.27 136.748,45.415 129.925,45.415
  pour cut-out: 131.445,36.392 119.918,36.392 119.918,40.392 131.445,40.392
Bottom Layer:
  pour cut-out: 129.92,-1.27 136.786,-1.27 136.748,45.415 129.925,45.415
  pour cut-out: 35.56,27.407 34.29,27.407 34.29,26.137 35.56,26.137

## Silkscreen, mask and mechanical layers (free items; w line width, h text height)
Top Overlay:
  drawing of 82 lines, arcs and shapes, not listed
  text "nRF ONLY" at 97.765,62.052 h1.78
  text "DEFAULT" at 104.877,62.052 h1.78
  text "GND" at 91.389,61.709 h1.78
  text "GND" at 11.125,61.62 h1.78
  text ".PCBNumber" at 116.028,61.468 h2.03
  text ".PCBRevision" at 116.093,60.165 h1.52
  text "GND" at 123.698,58.42 h1.78
  text "LED1" at 109.622,54.654 h2.03
  text "LED2" at 115.82,54.654 h2.03
  text "Debug out" at 0.406,54.127 h2.03
  text "P0.11" at 87.757,52.781 h1.78
  text "P0.12" at 99.568,52.781 h1.78
  text "LED3" at 109.495,50.869 h2.03
  text "LED4" at 115.845,50.869 h2.03
  text "VDD_HV" at 1.016,50.775 h1.4
  text "P0.13" at 87.757,50.241 h1.78
  text "P0.14" at 99.568,50.241 h1.78
  text "P0.27" at 19.304,49.886 h1.78 r90
  text "P0.26" at 21.844,49.886 h1.78 r90
  text "P0.02" at 24.384,49.886 h1.78 r90
  text "GND" at 26.924,49.886 h1.78 r90
  text "P1.15" at 29.464,49.886 h1.78 r90
  text "P1.14" at 32.004,49.886 h1.78 r90
  text "P1.13" at 34.544,49.886 h1.78 r90
  text "P1.12" at 37.084,49.886 h1.78 r90
  text "P1.11" at 39.624,49.886 h1.78 r90
  text "P1.10" at 42.164,49.886 h1.78 r90
  text "P1.08" at 46.228,49.886 h1.78 r90
  text "P1.07" at 48.768,49.886 h1.78 r90
  text "P1.06" at 51.308,49.886 h1.78 r90
  text "P1.05" at 53.848,49.886 h1.78 r90
  text "P1.04" at 56.388,49.886 h1.78 r90
  text "P1.03" at 58.928,49.886 h1.78 r90
  text "P1.02" at 61.468,49.886 h1.78 r90
  text "P0.10" at 69.088,49.886 h1.78 r90
  text "P0.09" at 71.628,49.886 h1.78 r90
  text "P0.08" at 74.168,49.886 h1.78 r90
  text "P0.07" at 76.708,49.886 h1.78 r90
  text "P0.06" at 79.248,49.886 h1.78 r90
  text "P0.05" at 81.788,49.886 h1.78 r90
  text "P0.01" at 84.328,49.886 h1.78 r90
  text "P0.00" at 86.868,49.886 h1.78 r90
  text "P0.15" at 87.757,47.701 h1.78
  text "P0.16" at 99.568,47.701 h1.78
  text "nRF current" at 0.965,47.193 h2.03
  text "measurement" at 0.483,45.898 h2.03
  text "Alt." at 79.756,45.339 h1.78
  text "Def." at 83.439,45.339 h1.78
  text "P0.17" at 87.757,45.161 h1.78
  text "P0.18" at 99.568,45.161 h1.78
  text "GPIO" at 102.997,44.958 h1.52
  text "XTAL" at 102.997,43.688 h1.52
  text "P0.19" at 87.757,42.621 h1.78
  text "P0.20" at 99.568,42.621 h1.78
  text "VDD" at 1.016,42.57 h1.4
  text "VTG" at 24.308,41.056 h1.4 r90
  text "VDD / nRF" at 19.761,40.98 h1.4 r90
  text "VDD / nRF'" at 22.301,40.98 h1.4 r90
  text "(ARDUINO D0) P1.01" at 64.059,40.777 h1.78 r90
  text "SWD / IO" at 27.508,40.752 h1.4 r90
  text "SWD / CLK" at 30.048,40.752 h1.4 r90
  text "SWO" at 31.928,40.74 h1.4 r90
  text "TRACE" at 80.391,40.513 h1.78
  text "P0.21" at 87.757,40.081 h1.78
  text "P0.22" at 99.568,40.081 h1.78
  text "VIN / 3-5V" at 40.081,39.993 h1.4 r90
  text "RESET" at 34.519,39.811 h1.4 r90
  text "VDD / nRF_HV" at 42.621,39.028 h1.4 r90
  text "VDD / nRF_HV'" at 45.161,39.028 h1.4 r90
  text "GND / DETECT" at 37.617,38.963 h1.4 r90
  text "P0.23" at 87.757,37.541 h1.78
  text "P0.24" at 99.568,37.541 h1.78
  text "P1.14" at 57.767,35.082 h1.52
  text "5V" at 69.248,35.031 h1.52
  text "P0.25" at 87.757,35.001 h1.78
  text "P1.00" at 99.568,35.001 h1.78
  text "Li-Po   VDD   USB" at 18.313,34.95 h1.78
  text "nRF power source" at 17.424,33.299 h2.03
  text "P1.13" at 69.248,32.567 h1.52
  text "P1.15" at 57.717,32.542 h1.52
  text "P1.09" at 87.757,32.461 h1.78
  text "GND" at 99.568,32.461 h1.78
  text "DETECT" at 69.16,30.074 h1.52
  text "RESET" at 56.955,30.002 h1.52
  text "Debug in" at 79.477,23.12 h2.03
  text "External supply" at 0.279,22.454 h2.03
  text "SB20-22" at 106.934,22.225 h1.52 r90
  text "SB10-12" at 110.465,22.225 h1.52 r90
  text "SB13-15" at 118.364,21.463 h1.52 r90
  text "SB23-25" at 121.92,21.463 h1.52 r90
  text "-" at 13.741,19.939 h1.52
  text "+" at 13.741,17.399 h1.52
  text "Button 1" at 102.594,17.19 h2.29
  text "Button 2" at 112.641,17.19 h2.29
  text "Li-po" at 3.251,15.088 h2.03
  text "-" at 5.715,13.513 h1.02
  text "+" at 5.715,10.973 h1.02
  text "N.C." at 46.253,10.465 h1.78 r90
  text "VDD" at 28.365,10.462 h1.78 r90
  text "VDD" at 30.905,10.462 h1.78 r90
  text "RESET" at 33.445,10.462 h1.78 r90
  text "VDD" at 35.985,10.462 h1.78 r90
  text "5V" at 38.525,10.462 h1.78 r90
  text "GND" at 41.065,10.462 h1.78 r90
  text "GND" at 43.605,10.462 h1.78 r90
  text "P0.03 (A0)" at 51.225,10.462 h1.78 r90
  text "P0.04" at 53.765,10.462 h1.78 r90
  text "P0.28" at 56.305,10.462 h1.78 r90
  text "P0.29" at 58.845,10.462 h1.78 r90
  text "P0.30" at 61.385,10.462 h1.78 r90
  text "P0.31" at 63.925,10.462 h1.78 r90
  text "NFC" at 123.123,9.926 h2.29
  text "Button 4" at 112.691,8.011 h2.29
  text "Button 3" at 102.518,8 h2.29
  text "IF BOOT/RESET" at 71.907,7.785 h2.03
  text "nRF USB" at 86.298,7.131 h2.29
  text "VEXT   nRF" at 16.662,6.909 h2.03
  text "GND" at 69.393,5.156 h1.78
  text "Power" at 11.506,3.2 h2.03 r90
  text "nRF52840-DK" at 132.283,0.914 h2.54 r90
  text "GND" at 68.402,0.761 h1.78
  text "ON" at 2.911,0.229 h1.78
  text "OFF" at 5.655,0.229 h1.78
  text "OFF" at 18.009,0.203 h1.78
  text "ON" at 21.438,0.203 h1.78
Bottom Overlay:
  drawing of 1284 lines, arcs and shapes, not listed
  text "J-Link" at 117.897,62.424 h1.45 r90
  text "www.segger.com" at 119.047,62.343 h1.68 r90
  text "Pb" at 6.415,60.623 h3.05 r90
  text "TM" at 117.475,58.954 h0.94 r90
  text "S" at 116.037,58.741 h1.35 r90
  text "E" at 116.037,57.851 h1.35 r90
  text "Technology" at 117.897,57.672 h1.45 r90
  text "G" at 116.037,57.067 h1.35 r90
  text "G" at 116.037,56.077 h1.35 r90
  text "E" at 116.037,55.053 h1.35 r90
  text "R" at 116.037,54.217 h1.35 r90
  text "P0.27" at 19.303,53.111 h1.65 r90
  text "P0.26" at 21.843,53.111 h1.65 r90
  text "P0.02" at 24.383,53.111 h1.65 r90
  text "GND" at 26.924,53.111 h1.65 r90
  text "P1.15" at 29.463,53.111 h1.65 r90
  text "P1.14" at 32.003,53.111 h1.65 r90
  text "P1.13" at 34.543,53.111 h1.65 r90
  text "P1.12" at 37.083,53.111 h1.65 r90
  text "P1.11" at 39.623,53.111 h1.65 r90
  text "P1.10" at 42.163,53.111 h1.65 r90
  text "P1.08" at 46.227,53.111 h1.65 r90
  text "P1.07 (D6)" at 48.768,53.111 h1.65 r90
  text "P1.06 (D5)" at 51.308,53.111 h1.65 r90
  text "P1.05 (D4)" at 53.848,53.111 h1.65 r90
  text "P1.04 (D3)" at 56.388,53.111 h1.65 r90
  text "P1.03 (D2)" at 58.928,53.111 h1.65 r90
  text "P1.02 (D1)" at 61.468,53.111 h1.65 r90
  text "P1.01 (ARDUINO D0)" at 64.008,53.111 h1.65 r90
  text "P0.10" at 69.088,53.111 h1.78 r90
  text "P0.09" at 71.628,53.111 h1.78 r90
  text "P0.08" at 74.168,53.111 h1.78 r90
  text "P0.07" at 76.708,53.111 h1.78 r90
  text "P0.06" at 79.248,53.111 h1.78 r90
  text "P0.05" at 81.788,53.111 h1.78 r90
  text "P0.01" at 84.328,53.111 h1.78 r90
  text "P0.00" at 86.843,53.111 h1.78 r90
  text "(SCL)" at 20.421,52.07 h1.65 r90
  text "(SDA)" at 22.961,52.07 h1.65 r90
  text "(AREF)" at 25.501,52.07 h1.65 r90
  text "(D13)" at 30.581,52.07 h1.65 r90
  text "(D12)" at 33.121,52.07 h1.65 r90
  text "(D11)" at 35.661,52.07 h1.65 r90
  text "(D10)" at 38.201,52.07 h1.65 r90
  text "(D9)" at 40.741,52.07 h1.65 r90
  text "(D8)" at 43.281,52.07 h1.65 r90
  text "(D7)" at 47.345,52.07 h1.65 r90
  text "GPIO" at 76.911,48.701 h1.99 r90
  text "P0.00" at 80.747,48.641 h1.91 r90
  text "P0.01" at 86.131,48.641 h1.91 r90
  text "P0.11" at 90.17,48.641 h1.91 r90
  text "P0.12" at 92.862,48.641 h1.91 r90
  text "P0.24" at 95.555,48.641 h1.91 r90
  text "P0.25" at 98.247,48.641 h1.91 r90
  text "P0.13" at 100.94,48.641 h1.91 r90
  text "P0.14" at 103.632,48.641 h1.91 r90
  text "P0.15" at 106.324,48.641 h1.91 r90
  text "P0.16" at 109.017,48.641 h1.91 r90
  text "P0.17" at 111.709,48.641 h1.91 r90
  text "P0.19" at 114.402,48.641 h1.91 r90
  text "P0.20" at 117.094,48.641 h1.91 r90
  text "P0.21" at 119.786,48.641 h1.91 r90
  text "P0.22" at 122.479,48.641 h1.91 r90
  text "P0.23" at 125.171,48.641 h1.91 r90
  text "Function" at 76.911,43.231 h1.99 r90
  text "Button 4" at 98.247,42.965 h1.91 r90
  text "Button 2" at 92.862,42.942 h1.91 r90
  text "Button 3" at 95.555,42.949 h1.91 r90
  text "Button 1" at 90.17,42.846 h1.91 r90
  text "LED 4" at 109.017,41.922 h1.91 r90
  text "LED 2" at 103.632,41.899 h1.91 r90
  text "LED 3" at 106.324,41.905 h1.91 r90
  text "GPIO" at 27.33,41.805 h1.99 r90
  text "P0.05" at 29.82,41.783 h1.91 r90
  text "P0.06" at 32.512,41.783 h1.91 r90
  text "P0.07" at 35.204,41.783 h1.91 r90
  text "P0.08" at 37.897,41.783 h1.91 r90
  text "P0.18" at 40.589,41.783 h1.91 r90
  text "P1.00" at 43.282,41.783 h1.91 r90
  text "P0.09" at 52.222,41.783 h1.91 r90
  text "P0.10" at 56.794,41.783 h1.91 r90
  text "LED 1" at 100.94,41.803 h1.91 r90
  text "DIO3" at 125.171,41.482 h1.91 r90
  text "DIO0" at 117.094,41.476 h1.91 r90
  text "DIO2" at 122.479,41.476 h1.91 r90
  text "DIO1" at 119.786,41.38 h1.91 r90
  text "CLK" at 114.402,41.301 h1.91 r90
  text "XL2" at 86.131,41.111 h1.91 r90
  text "XL1" at 80.747,41.015 h1.91 r90
  text "CS" at 111.709,40.693 h1.91 r90
  text "SWDCLK" at 48.666,39.218 h1.91 r90
  text "SWDIO" at 45.974,38.329 h1.91 r90
  text "Function" at 27.33,36.335 h1.99 r90
  text "RESET" at 40.564,35.457 h1.91 r90
  text "SB13/23" at 111.709,35.23 h1.91 r90
  text "SB11/21" at 114.402,35.23 h1.91 r90
  text "SB12/22" at 117.094,35.23 h1.91 r90
  text "SB14/24" at 119.786,35.23 h1.91 r90
  text "SB15/25" at 122.479,35.23 h1.91 r90
  text "SB10/20" at 125.171,35.23 h1.91 r90
  text "NFC2" at 56.82,34.816 h1.91 r90
  text "NFC1" at 52.248,34.72 h1.91 r90
  text "SB2" at 79.4,34.671 h1.91 r90
  text "SB4" at 82.093,34.671 h1.91 r90
  text "SB1" at 84.785,34.671 h1.91 r90
  text "SB3" at 87.478,34.671 h1.91 r90
  text "SB5" at 100.94,34.671 h1.91 r90
  text "SB6" at 103.632,34.671 h1.91 r90
  text "SB7" at 106.324,34.671 h1.91 r90
  text "SB8" at 109.017,34.671 h1.91 r90
  text "SWO" at 43.282,34.667 h1.91 r90
  text "RXD" at 37.897,34.39 h1.91 r90
  text "TXD" at 32.512,34.338 h1.91 r90
  text "CTS" at 35.204,34.318 h1.91 r90
  text "RTS" at 29.82,34.296 h1.91 r90
  text "Short" at 76.911,34.155 h1.99 r90
  text "HW" at 27.73,28.448 h1.99 r90
  text "IF / MCU" at 43.409,28.067 h1.78 r90
  text "GPIO" at 85.083,27.927 h1.78 r90
  text "GPIO" at 120.015,27.927 h1.78 r90
  text "GPIO" at 34.773,27.813 h1.78 r90
  text "GPIO" at 57.93,26.381 h1.78 r90
  text "HW" at 76.911,25.519 h1.99 r90
  text "N.C" at 54.864,25.273 h1.27 r90
  text "SB2x" at 115.443,25.057 h1.27 r90
  text "SB1x" at 117.729,25.057 h1.27 r90
  text "PIN" at 50.883,24.171 h1.78 r90
  text "MEM" at 120.015,23.253 h1.78 r90
  text "VDD" at 101.803,23.126 h1.78 r90
  text "PIN" at 80.574,22.364 h1.78 r90
  text "PIN" at 115.57,22.364 h1.78 r90
  text "0R" at 57.658,22.225 h1.27 r90
  text "IF OFF" at 38.735,21.209 h1.78 r90
  text "NFC" at 53.957,21.224 h1.78 r90
  text "Button 2" at 109.017,18.158 h1.91 r90
  text "Button 1" at 106.324,18.061 h1.91 r90
  text "Funct." at 103.835,17.355 h1.99 r90
  text "Function" at 116.916,17.284 h1.78 r90
  text "Default" at 124.714,17.183 h1.78 r90
  text "CTS" at 111.709,16.429 h1.91 r90
  text "P0.03 (A0)" at 51.181,16.012 h1.65 r90
  text "P0.04 (A1)" at 53.721,16.002 h1.65 r90
  text "P0.28 (A2)" at 56.261,16.002 h1.65 r90
  text "P0.29 (A3)" at 58.801,16.002 h1.65 r90
  text "P0.31 (A5)" at 63.881,16.019 h1.65 r90
  text "P0.30 (A4)" at 61.335,15.985 h1.65 r90
  text "RESET" at 33.522,14.272 h1.65 r90
  text "GND" at 43.605,13.103 h1.65 r90
  text "GND" at 41.142,12.95 h1.65 r90
  text "N.C." at 46.272,12.95 h1.78 r90
  text "VDD" at 28.448,12.87 h1.65 r90
  text "VDD" at 30.988,12.87 h1.65 r90
  text "VDD" at 36.068,12.87 h1.65 r90
  text "5V" at 38.633,11.828 h1.65 r90
  text "HW" at 114.249,11.676 h1.99 r90
  text "P0.11" at 106.324,10.579 h1.91 r90
  text "P0.12" at 109.017,10.579 h1.91 r90
  text "P0.07" at 111.709,10.579 h1.91 r90
  text "Def." at 103.835,9.957 h1.99 r90
  text "Alternative" at 124.46,9.055 h1.78 r90
  text "TRACE / SW" at 121.234,8.648 h1.78 r90
  text "P1.07" at 106.324,5.626 h1.91 r90
  text "P1.08" at 109.017,5.626 h1.91 r90
  text "P0.04" at 111.709,5.626 h1.91 r90
  text "Alt." at 103.835,4.691 h1.99 r90
Mechanical 1:
  the board outline again, w0.254
Mechanical 4:
  lines w0.165: 8.551,31.901 9.728,31.901 cw(c9.728,31.592) 9.947,31.811 10.031,31.727 ccw(c10.566,32.263) 10.566,31.505 ccw(c10.566,32.259) 11.1,31.726 11.184,31.81 cw(c11.405,31.589) 11.405,31.901 13.147,31.901 ccw(c13.147,32.944) 13.884,32.207 15.112,33.435 ; 8.552,32.259 11.506,32.259 ccw(c11.506,32.571) 11.727,32.35 11.811,32.434 cw(c12.344,31.901) 12.344,32.655 cw(c12.344,31.897) 12.88,32.433 12.964,32.349 ccw(c13.183,32.568) 13.183,32.259 ; 13.153,32.259 ccw(c13.153,32.935) 13.631,32.457 14.84,33.666 ; 14.837,33.669 cw(c16.073,32.433) 16.073,34.181 ; 15.102,33.425 cw(c16.063,32.464) 16.063,33.823 34.407,33.823 ; 16.063,34.181 34.407,34.181 ; 89.242,10.697 89.242,12.23 cw(c91.338,12.23) 91.338,14.326 ccw(c91.338,16.411) 92.813,14.936 94.183,16.307 ; 89.6,10.697 89.6,12.232 cw(c91.338,12.232) 91.338,13.97 ccw(c91.338,16.418) 93.069,14.687 93.522,15.139 ccw(c93.294,16.129) 94.284,15.901 ; 94.204,16.333 cw(c95.199,16.129) 94.995,17.124 ; 94.284,15.902 106.34,27.958 cw(c108.136,26.162) 108.136,28.702 113.295,28.702 ; 94.998,17.121 106.088,28.211 cw(c108.136,26.162) 108.136,29.06 113.295,29.06 ccw(c113.295,29.693) 113.928,29.693 113.928,30.023 ; 112.977,34.061 ccw(c113.89,34.061) 113.244,33.415 113.741,32.918 cw(c113.29,32.467) 113.928,32.467 113.928,32.004 ; 112.982,34.061 112.982,34.299 ; 113.295,28.702 ccw(c113.295,29.693) 114.286,29.693 114.286,30.023 ; 113.335,34.289 113.335,34.061 ccw(c113.89,34.061) 113.498,33.669 113.994,33.172 cw(c113.29,32.467) 114.286,32.467 114.286,32.004
  lines w0.762: 121.681,38.379 126.25,38.379
  text "50ohm impedance" at 115.824,39.37 h1.02
  text "90ohm differensial impedance" at 7.417,35.382 h1.02
  text "90ohm differensial impedance" at 90.119,14.402 h1.02 r45
Mechanical 7:
  drawing of 47 lines, arcs and shapes, not listed
Mechanical 8:
  drawing of 47 lines, arcs and shapes, not listed
Mechanical 24:
  lines w0.165: 8.551,31.901 9.728,31.901 cw(c9.728,31.592) 9.947,31.811 10.031,31.727 ccw(c10.566,32.263) 10.566,31.505 ccw(c10.566,32.259) 11.1,31.726 11.184,31.81 cw(c11.405,31.589) 11.405,31.901 13.147,31.901 ccw(c13.147,32.944) 13.884,32.207 15.112,33.435 ; 8.552,32.259 11.506,32.259 ccw(c11.506,32.571) 11.727,32.35 11.811,32.434 cw(c12.344,31.901) 12.344,32.655 cw(c12.344,31.897) 12.88,32.433 12.964,32.349 ccw(c13.183,32.568) 13.183,32.259 ; 13.153,32.259 ccw(c13.153,32.935) 13.631,32.457 14.84,33.666 ; 14.837,33.669 cw(c16.073,32.433) 16.073,34.181 ; 15.102,33.425 cw(c16.063,32.464) 16.063,33.823 34.407,33.823 ; 16.063,34.181 34.407,34.181 ; 89.242,10.697 89.242,12.23 cw(c91.338,12.23) 91.338,14.326 ccw(c91.338,16.411) 92.813,14.936 94.183,16.307 ; 89.6,10.697 89.6,12.232 cw(c91.338,12.232) 91.338,13.97 ccw(c91.338,16.418) 93.069,14.687 93.522,15.139 ccw(c93.294,16.129) 94.284,15.901 ; 94.204,16.333 cw(c95.199,16.129) 94.995,17.124 ; 94.284,15.902 106.34,27.958 cw(c108.136,26.162) 108.136,28.702 113.295,28.702 ; 94.998,17.121 106.088,28.211 cw(c108.136,26.162) 108.136,29.06 113.295,29.06 ccw(c113.295,29.693) 113.928,29.693 113.928,30.023 ; 112.977,34.061 ccw(c113.89,34.061) 113.244,33.415 113.741,32.918 cw(c113.29,32.467) 113.928,32.467 113.928,32.004 ; 112.982,34.061 112.982,34.299 ; 113.295,28.702 ccw(c113.295,29.693) 114.286,29.693 114.286,30.023 ; 113.335,34.289 113.335,34.061 ccw(c113.89,34.061) 113.498,33.669 113.994,33.172 cw(c113.29,32.467) 114.286,32.467 114.286,32.004
  lines w0.762: 121.681,38.379 126.25,38.379
  text "50ohm impedance" at 115.824,39.37 h1.02
  text "90ohm differensial impedance" at 7.417,35.382 h1.02
  text "90ohm differensial impedance" at 90.119,14.402 h1.02 r45

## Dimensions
132.969,62.484 to 136.175,65.69 on Mechanical 3
0,1.016 to 90.17,55.88 on Mechanical 3
0,1.016 to 133.985,1.016 on Mechanical 3
0,1.016 to 136.525,10.16 on Mechanical 3
0,1.016 to 13.97,7.62 on Mechanical 3
0,1.016 to 15.24,55.88 on Mechanical 3
0,1.016 to 66.04,12.7 on Mechanical 3
0,1.016 to 96.52,7.62 on Mechanical 3
132.969,0 to 132.969,63.5 on Mechanical 3
132.969,0 to 96.52,7.62 on Mechanical 3
132.969,0 to 66.04,12.7 on Mechanical 3
132.969,0 to 66.04,40.64 on Mechanical 3
132.969,0 to 15.24,55.88 on Mechanical 3
132.969,0 to 128.27,46.355 on Mechanical 3
0,1.016 to 128.27,46.355 on Mechanical 3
